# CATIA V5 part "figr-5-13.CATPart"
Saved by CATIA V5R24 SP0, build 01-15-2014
Part number: Part1
Bounding box of the stored display mesh (mm): x 0 to 150, y -70 to 70, z -150 to 69.804
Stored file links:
  D:\KAVITA\CATIA V5-6R2014 Project_ Kavita\CATIA V5-6R2014_partfiles\Partfiles\c05_catia_v5-6r2014_prt\figr-5-13.CATPart
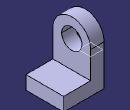
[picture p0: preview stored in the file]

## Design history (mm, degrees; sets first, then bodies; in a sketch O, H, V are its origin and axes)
Set1
  Plane1: type Normal, Curve edge [face of Pad1 | face of Pad1], RefPoint vertex of Pad2
Body1 (main body)
  Sketch1 on yz-plane, origin (0, 0, 0), H (0, 1, 0), V (0, 0, 1)
    arc A1 centre (0, 0) radius 70 from (70, 0) to (-70, 0) ccw
    point P1 (70, 0)
    point P2 (-70, 0)
    line L1 (-70, 0) -> (-70, -150)
    line L2 (-70, -150) -> (70, -150)
    line L3 (70, -150) -> (70, 0)
    circle A2 centre (0, 0) radius 37.5
    radius A1 = 70
    radius A2 = 37.5
    distance O L2 = 150
    coincidence: P1 H, P2 H
    tangency: L1 A1, L3 A1
    horizontal: L2 H
  Pad1: profile Sketch1, direction (1, 0, 0), length 50
  Sketch2 on face of Pad1, origin (50, 0, 0), H (0, 1, 0), V (0, 0, 1)
    line L1 (-70, -150) -> (70, -150)
    line L2 (70, -150) -> (70, -100)
    line L3 (70, -100) -> (-70, -100)
    line L4 (-70, -100) -> (-70, -150)
    reference projected line E1 (-70, -150) -> (70, -150) from edge [face of Pad1 | face of Pad1]
    reference projected line E2 (-70, 0) -> (-70, -150) from edge [face of Pad1 | face of Pad1]
    reference projected line E3 (70, -150) -> (70, 0) from edge [face of Pad1 | face of Pad1]
    length L2 = 50
    horizontal: L1 H, L3 H
    vertical: L2 V, L4 V
    coincidence: L1 E1, E2 L4, L2 E3
  Pad2: profile Sketch2, direction (1, 0, 0), length 100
